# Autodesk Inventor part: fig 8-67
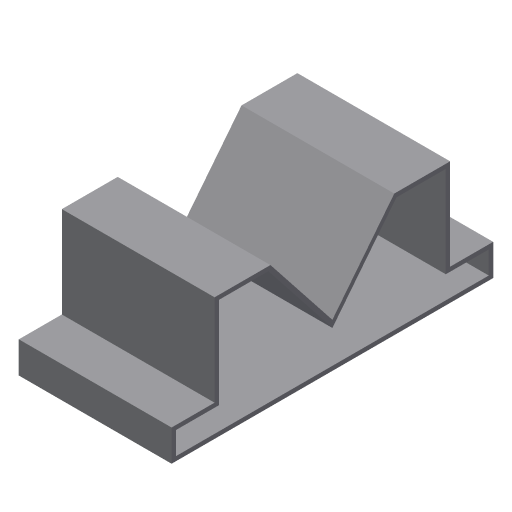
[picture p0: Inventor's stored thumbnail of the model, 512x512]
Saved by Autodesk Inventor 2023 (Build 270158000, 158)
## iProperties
Created: 2002-01
Part Number: fig 8-67
Document SubType Name: Modeling
Designer: ***
Density: 1 g/cm^3
Material: Generic
Appearance: Default
Control State: 0
Master: False
Checked Out: False
Shininess: 77.0
Length Units: 11269
Angle Units: 11279
Time Units: 11290
Mass Units: 11283
Length Display Precision: 3
Angle Display Precision: 2
Density: 0.0
Volumn: 0.0
Area: 0.0
PropertySet Name: Model Information
Author: ***
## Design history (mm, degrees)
node "Sketch1"
sketch "Sketch2"
  geometry: L1 (0, 0)-(-14.184, 17.961); L2 (-14.184, 17.961)-(-26.987, 17.961); L3 (-26.987, 17.961)-(-26.987, -2.947); L4 (-26.987, -2.947)-(-36.842, -2.947); L5 (-36.842, -2.947)-(-36.842, -10.132); L6 (26.987, 17.961)-(26.987, -2.947); L7 (14.184, 17.961)-(26.987, 17.961); L8 (26.987, -2.947)-(36.842, -2.947); L9 (36.842, -10.132)-(-36.842, -10.132); L10 (36.842, -2.947)-(36.842, -10.132); L11 (0, 0)-(14.184, 17.961)
  constraints: 22 end point, 2 horizontal, 2 parallel, 1 perpendicular
extrude "Extrusion1" new body sketch "Sketch2" distance "d0" = 35; taper "d1" = 0 deg
shell "Shell3" dims "d13" = 1
body "Solid1"
